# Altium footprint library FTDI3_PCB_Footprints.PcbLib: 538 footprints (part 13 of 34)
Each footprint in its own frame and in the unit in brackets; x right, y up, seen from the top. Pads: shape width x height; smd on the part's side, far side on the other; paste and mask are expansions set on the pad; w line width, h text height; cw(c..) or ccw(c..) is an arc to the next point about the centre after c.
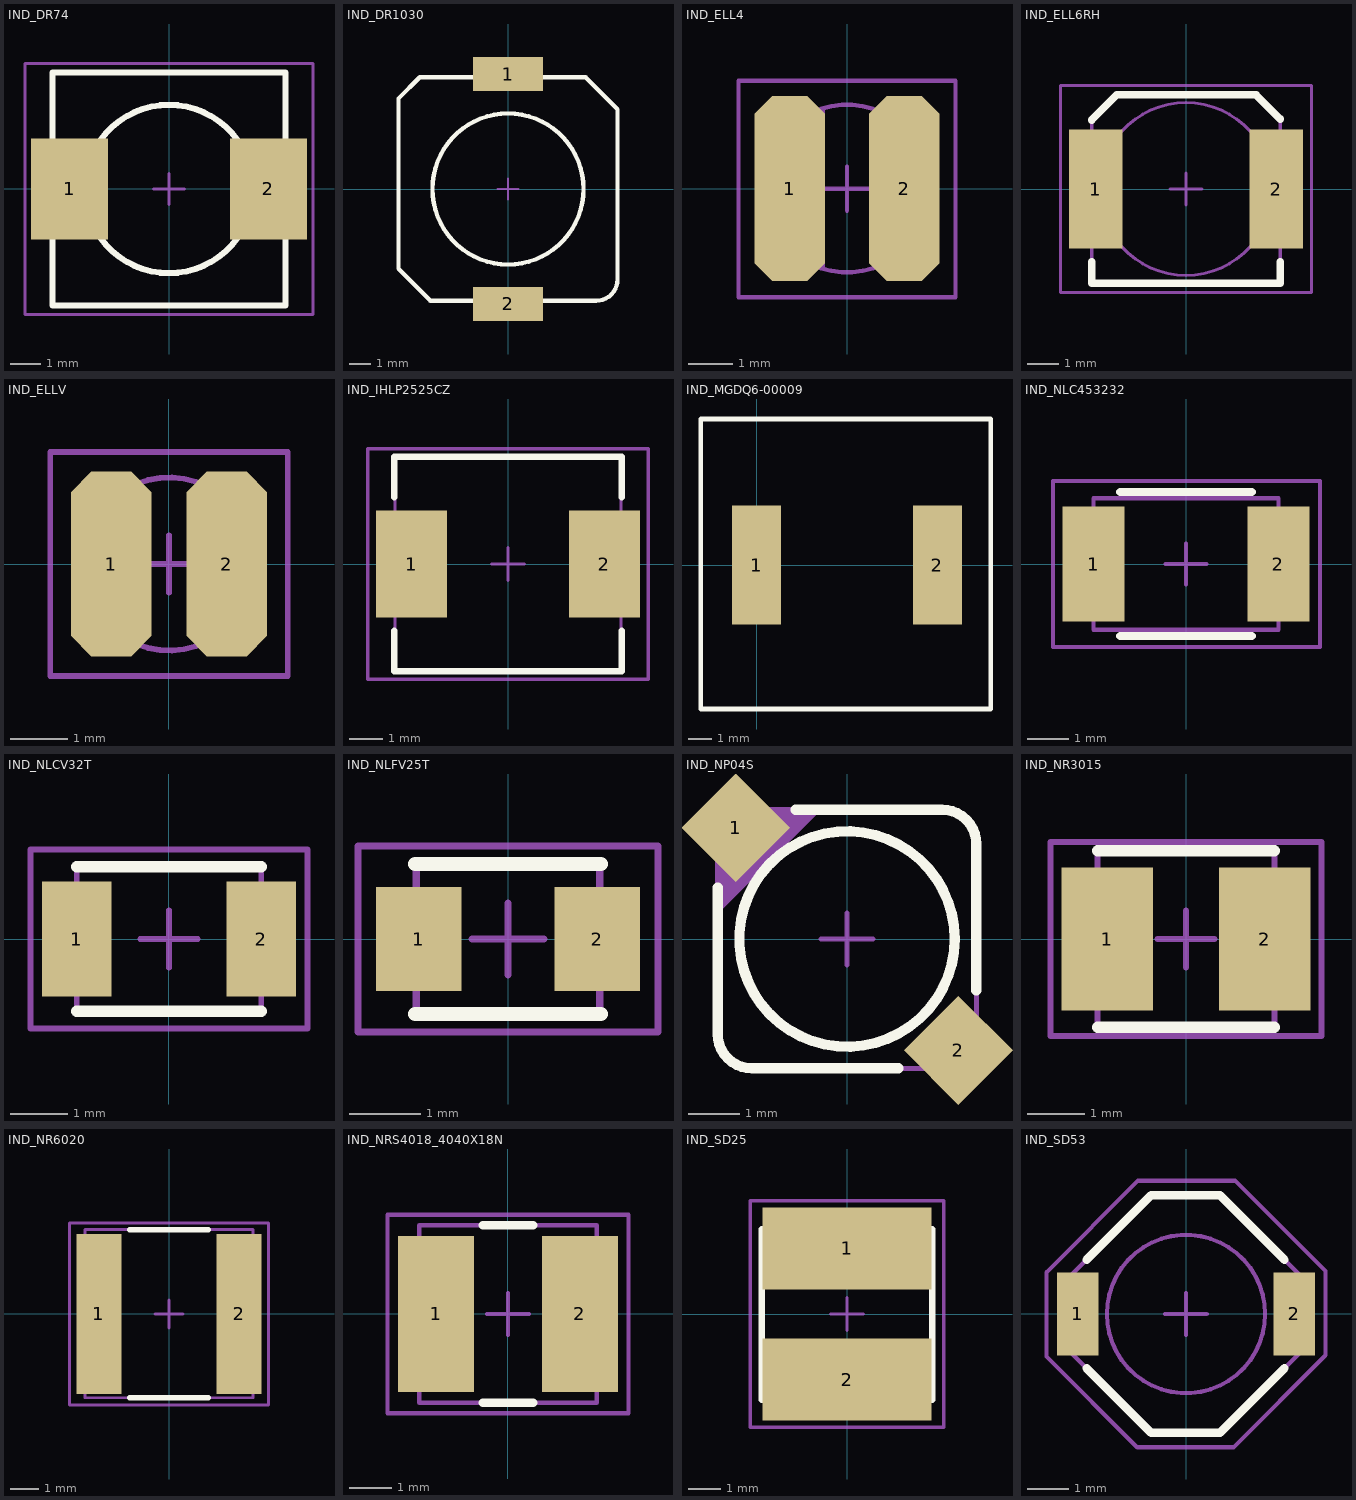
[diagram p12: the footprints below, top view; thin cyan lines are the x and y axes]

## IND_DR74 [mm] "DR Series  High Power Density,  High Efficiency, Shielded Inductors"
height 3.5
pads (2):
  rect 2.5x3.3 smd: 1(-3.25,0) 2(3.25,0)
Top Overlay:
  circle w0.2: c0,0 r2.75
  lines w0.2: -3.8,-3.8 3.8,-3.8 3.8,3.8 -3.8,3.8 -3.8,-3.8
M13_Assembly_Info:
  circle w0.1: c0,0 r2.75
  lines w0.1: -3.8,-3.8 3.8,-3.8 3.8,3.8 -3.8,3.8 -3.8,-3.8
M15_Country_Yard:
  lines w0.1: -0.5,0 0.5,0 ; 0,-0.5 0,0.5 ; -4.7,-4.1 4.7,-4.1 4.7,4.1 -4.7,4.1 -4.7,-4.1
3D body: height 0, standoff 0, extent -3.8,-3.8 3.8,3.8

## IND_DR1030 [mm] "TAIYO YUDEN Inductor, series NP04S"
height 3
pads (2):
  rect 3.3x1.6 smd: 1(0,5.4) 2(0,-5.4)
Top Overlay:
  circle w0.2: c0,0 r3.55
  lines w0.2: -5.15,-3.75 -5.15,4.25 -4.15,5.25 3.65,5.25 5.15,3.75 5.15,-4.25 cw(c4.15,-4.25) 4.15,-5.25 -3.65,-5.25 -5.15,-3.75
M13_Assembly_Info:
  circle w0.1: c0,0 r3.55
  lines w0.1: -5.15,-3.75 -5.15,4.25 -4.15,5.25 3.65,5.25 5.15,3.75 5.15,-4.25 cw(c4.15,-4.25) 4.15,-5.25 -3.65,-5.25 -5.15,-3.75
M15_Country_Yard:
  lines w0.1: -0.5,0 0.5,0 ; 0,-0.5 0,0.5
3D body: height 0, standoff 0, extent -5.15,-5.25 5.15,5.25

## IND_ELL4 [mm] "ELL4 SMD Choke Coils; Panasonic"
height 1.2
pads (2):
  oct 1.6x4.2 smd: 1(-1.3,0) 2(1.3,0)
M13_Assembly_Info:
  circle w0.1: c0,0 r1.9
  region: -0.5,-1.82 -0.74,-1.74 -1.06,-1.62 -1.58,-1.1 -1.58,-0.98 -1.76,-0.8 -1.76,-0.58 -1.86,-0.48 -1.86,-0.22 -1.9,-0.18 -1.88,-0.16 -1.88,0.46 -1.78,0.56 -1.78,0.76 -1.62,0.92 -1.62,1.06 -1.34,1.34 -1.34,1.36 -1.32,1.36 -1.06,1.62 -0.92,1.62 -0.76,1.78 -0.56,1.78 -0.5,1.84
M15_Country_Yard:
  lines w0.1: -0.5,0 0.5,0 ; 0,-0.5 0,0.5 ; -2.46,-2.46 -2.46,2.44 2.46,2.44 2.46,-2.46 -2.46,-2.46
3D body: height 1.2, standoff 0, extent -1.885,-1.9 1.9,1.893

## IND_ELL6RH [mm] "Panasonic; SMD Choke Coil"
height 2.8
pads (2):
  rect 1.7x3.8 smd: 1(-2.875,0) 2(2.875,0)
Top Overlay:
  lines w0.25: -3,-2.325 -3,-3 3,-3 3,-2.325 ; -3,2.2 -2.2,3 2.225,3 3,2.225
M13_Assembly_Info:
  circle w0.1: c0,0 r2.75
  lines w0.1: -3,-3 -3,2.2 -2.2,3 2.225,3 3,2.225 3,-3 -3,-3
M15_Country_Yard:
  lines w0.1: -0.5,0 0.5,0 ; 0,-0.5 0,0.5 ; -4,-3.3 4,-3.3 4,3.3 -4,3.3 -4,-3.3
3D body: height 2.8, standoff 0, extent -3,-3 3,3

## IND_ELLV [mm] "SMD Choke Coil; Panasonic; ELLV series"
height 1.5
pads (2):
  oct 1.4x3.2 smd: 1(-1,0) 2(1,0)
M13_Assembly_Info:
  circle w0.1: c0,0 r1.5
  region: -0.5,1.4 -0.5,-1.4 -0.58,-1.4 -0.7,-1.28 -0.78,-1.28 -0.9,-1.16 -0.94,-1.16 -1.08,-1.02 -1.1,-1.02 -1.1,-1 -1.24,-0.86 -1.24,-0.82 -1.36,-0.7 -1.36,-0.56 -1.44,-0.48 -1.44,-0.28 -1.5,-0.22 -1.5,0.28 -1.44,0.34 -1.44,0.5 -1.38,0.56 -1.38,0.66 -1.24,0.8 -1.24,0.86 -0.9,1.2 -0.84,1.2 -0.66,1.38 -0.52,1.38
M15_Country_Yard:
  lines w0.1: -0.5,0 0.5,0 ; 0,-0.5 0,0.5 ; -2.06,-1.94 -2.06,1.94 2.06,1.94 2.06,-1.94 -2.06,-1.94
3D body: height 1.5, standoff 0, extent -1.5,-1.467 1.488,1.527

## IND_IHLP2525CZ [mm] "Molded Inductor, 2-Leads, Body 6.9x6.5mm, IHLP2525CZ series, Vishay, IPC Medium Density"
height 3
pads (2):
  rect 2.15x3.25 smd: 1(-2.925,0) 2(2.925,0)
Top Overlay:
  lines w0.2: -3.45,-2.025 -3.45,-3.25 3.45,-3.25 3.45,-2.025 ; -3.45,2.025 -3.45,3.25 3.45,3.25 3.45,2.025
M13_Assembly_Info:
  lines w0.1: -3.43,-3.25 -3.43,3.25 3.43,3.25 3.43,-3.25 -3.43,-3.25
M15_Country_Yard:
  lines w0.1: -0.5,0 0.5,0 ; 0,-0.5 0,0.5 ; -4.25,-3.5 -4.25,3.5 4.25,3.5 4.25,-3.5 -4.25,-3.5
3D body: height 3, standoff 0, extent -3.43,-3.25 3.43,3.25

## IND_MGDQ6-00009 [mm] "10uH/5.4A Power inductor. Tayco Electronics"
pads (2):
  rect 2.13x5.13 smd: 1(0,0) 2(7.8,0)
Top Overlay:
  lines w0.2: -2.4,-6.2 10.1,-6.2 10.1,6.3 -2.4,6.3 -2.4,-6.2

## IND_NLC453232 [mm] "Molded Inductor, NLC453232 series, TDK; 2-Leads, Body 4.5x3.2mm (1812), IPC Medium Density"
height 3.2
pads (2):
  rect 1.5x2.8 smd: 1(-2.25,0) 2(2.25,0)
Top Overlay:
  lines w0.2: -1.6,-1.75 1.6,-1.75 ; -1.6,1.75 1.6,1.75
M13_Assembly_Info:
  lines w0.1: -2.25,-1.6 2.25,-1.6 2.25,1.6 -2.25,1.6 -2.25,-1.6
M15_Country_Yard:
  lines w0.1: -0.5,0 0.5,0 ; 0,-0.5 0,0.5 ; -3.24,-2.02 3.26,-2.02 3.26,2.02 -3.24,2.02 -3.24,-2.02
3D body: height 3.2, standoff 0, extent -2.25,-1.6 2.25,1.6

## IND_NLCV32T [mm] "Molded Inductor, NLCV32T series, TDK; 2-Leads, Body 3.2x2.5mm (1210), IPC Medium Density"
height 1.9
pads (2):
  rect 1.2x2 smd: 1(-1.6,0) 2(1.6,0)
Top Overlay:
  lines w0.2: -1.6,-1.25 1.6,-1.25 ; -1.6,1.25 1.6,1.25
M13_Assembly_Info:
  lines w0.1: -1.6,-1.25 1.6,-1.25 1.6,1.25 -1.6,1.25 -1.6,-1.25
M15_Country_Yard:
  lines w0.1: -0.5,0 0.5,0 ; 0,-0.5 0,0.5 ; -2.4,-1.55 -2.4,1.55 2.4,1.55 2.4,-1.55 -2.4,-1.55
3D body: height 0, standoff 0, extent -1.6,-1.25 1.6,1.25

## IND_NLFV25T [mm] "Molded Inductor, NLFV25T series, TDK; 2-Leads, Body 2.5x2.0mm, IPC Medium Density"
height 1.9
pads (2):
  rect 1.2x1.45 smd: 1(-1.25,0) 2(1.25,0)
Top Overlay:
  lines w0.2: -1.3,-1.05 1.3,-1.05 ; -1.3,1.05 1.3,1.05
M13_Assembly_Info:
  lines w0.1: -1.285,-1.05 1.285,-1.05 1.285,1.05 -1.285,1.05 -1.285,-1.05
M15_Country_Yard:
  lines w0.1: -0.5,0 0.5,0 ; 0,-0.5 0,0.5 ; -2.1,-1.3 2.1,-1.3 2.1,1.3 -2.1,1.3 -2.1,-1.3
3D body: height 1.9, standoff 0, extent -1.285,-1.05 1.285,1.05

## IND_NP04S [mm] "TAIYO YUDEN Inductor, series NP04S"
height 3
pads (2):
  rect 1.5x1.5 smd rot 45: 1(-2.16,2.16) 2(2.16,-2.16)
Top Overlay:
  circle w0.2: c0,0 r2.09
  lines w0.2: -2.51,1 -2.51,-1.84 ccw(c-1.84,-1.84) -1.84,-2.51 1,-2.51 ; -1,2.51 1.84,2.51 cw(c1.84,1.84) 2.51,1.84 2.51,-1
M13_Assembly_Info:
  circle w0.1: c0,0 r2.09
  region: -1.81,2.51 -0.5,2.51 -2.51,0.49 -2.51,1.82
  lines w0.1: -2.51,1.81 -1.81,2.51 1.84,2.51 cw(c1.84,1.84) 2.51,1.84 2.51,-1.81 1.81,-2.51 -1.84,-2.51 cw(c-1.84,-1.84) -2.51,-1.84 -2.51,1.82
M15_Country_Yard:
  lines w0.1: -0.5,0 0.5,0 ; 0,-0.5 0,0.5
3D body: height 0, standoff 0, extent -2.51,-2.51 2.51,2.51

## IND_NR3015 [mm] "Precision Wire Wound Inductor, 2-Leads, Body 3.00x3.00mm, IPC Medium Density"
height 1.5
pads (2):
  rect 1.6x2.5 smd: 1(-1.38,0) 2(1.38,0)
Top Overlay:
  lines w0.2: -1.55,-1.55 1.55,-1.55 ; -1.55,1.55 1.55,1.55
M13_Assembly_Info:
  lines w0.1: -1.55,-1.55 -1.55,1.55 1.55,1.55 1.55,-1.55 -1.55,-1.55
M15_Country_Yard:
  lines w0.1: -0.5,0 0.5,0 ; 0,-0.5 0,0.5 ; -2.375,-1.7 -2.375,1.7 2.375,1.7 2.375,-1.7 -2.375,-1.7
3D body: height 1.5, standoff 0, extent -1.55,-1.55 1.55,1.55

## IND_NR6020 [mm] "Inductor, NR6020 series, Taiyo Yuden"
height 2
pads (2):
  rect 1.6x5.7 smd: 1(-2.5,0) 2(2.5,0)
Top Overlay:
  lines w0.2: -1.4,-2.99 1.4,-2.99 ; -1.4,3.01 1.4,3.01
M13_Assembly_Info:
  lines w0.1: -3,-2.99 -3,3.01 3,3.01 3,-2.99 -3,-2.99
M15_Country_Yard:
  lines w0.1: -0.5,0 0.5,0 ; 0,-0.5 0,0.5 ; -3.55,-3.25 -3.55,3.25 3.55,3.25 3.55,-3.25 -3.55,-3.25
3D body: height 2, standoff 0, extent -3,-2.99 3,3.01

## IND_NRS4018_4040X18N [mm] "Molded Inductor, 2-Leads, Body 4.0x4.0mm, IPC Medium Density"
height 1.8
pads (2):
  rect 1.8x3.7 smd: 1(-1.7,0) 2(1.7,0)
Top Overlay:
  lines w0.2: -0.6,-2.1 0.6,-2.1 ; -0.6,2.1 0.6,2.1
M13_Assembly_Info:
  lines w0.1: -2.1,-2.1 -2.1,2.1 2.1,2.1 2.1,-2.1 -2.1,-2.1
M15_Country_Yard:
  lines w0.1: -0.5,0 0.5,0 ; 0,-0.5 0,0.5 ; -2.85,-2.35 -2.85,2.35 2.85,2.35 2.85,-2.35 -2.85,-2.35
3D body: height 1.8, standoff 0, extent -2.1,-2.1 2.1,2.1

## IND_SD25 [mm] "SD25 series, Cooper Bussmann, High Power Density,  Low Profile, Shielded Inductor"
height 2.5
pads (2):
  rect 5.15x2.5 smd: 1(0,2) 2(0,-2)
Top Overlay:
  lines w0.2: -2.6,-2.61 2.6,-2.61 2.6,2.59 -2.6,2.59 -2.6,-2.61
M13_Assembly_Info:
  lines w0.1: -2.6,-2.61 -2.6,2.59 2.6,2.59 2.6,-2.61 -2.6,-2.61
M15_Country_Yard:
  lines w0.1: -0.5,0 0.5,0 ; 0,-0.5 0,0.5 ; -2.95,-3.45 -2.95,3.45 2.95,3.45 2.95,-3.45 -2.95,-3.45
3D body: height 2.5, standoff 0, extent -2.6,-2.61 2.6,2.59

## IND_SD53 [mm] "SD53 series, Coiltronics/Cooper Bussmann, High Power Density,  Low Profile, Shielded Inductor"
height 3
pads (2):
  rect 1x2 smd: 1(-2.6,0) 2(2.6,0)
Top Overlay:
  lines w0.2: -2.385,-1.302 -0.837,-2.85 0.817,-2.85 2.365,-1.302 ; -2.385,1.302 -0.837,2.85 0.817,2.85 2.365,1.302
M13_Assembly_Info:
  circle w0.1: c0,0 r1.9
  lines w0.1: -2.85,-0.837 -2.85,0.837 -0.837,2.85 0.817,2.85 2.85,0.817 2.85,-0.817 0.817,-2.85 -0.837,-2.85 -2.85,-0.837
M15_Country_Yard:
  lines w0.1: -0.5,0 0.5,0 ; 0,-0.5 0,0.5 ; -3.35,-1.02 -1.17,-3.2 1.14,-3.2 3.35,-0.99 3.35,1.03 1.18,3.2 -1.15,3.2 -3.35,1 -3.35,-1.02
3D body: height 3, standoff 0, extent -2.85,-2.85 2.85,2.85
